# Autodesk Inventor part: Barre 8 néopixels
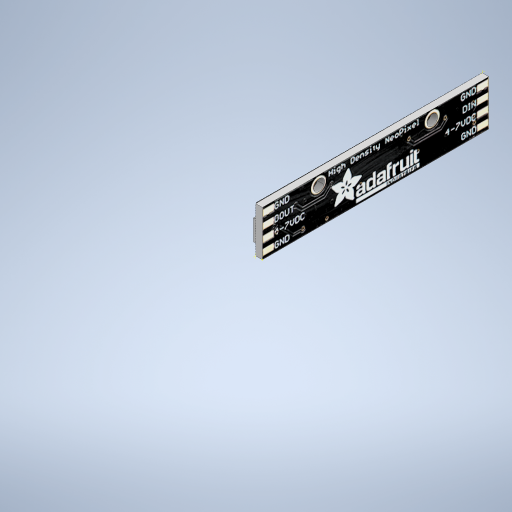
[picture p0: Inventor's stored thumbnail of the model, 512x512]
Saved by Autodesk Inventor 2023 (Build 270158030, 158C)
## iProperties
Created: 2022-11
Part Number: Barre 8 néopixels
Material: Générique
Document SubType Name: Modeling
Designer: ecuenot
Density: 1 g/cm^3
Appearance: Par défaut
Author: ecuenot
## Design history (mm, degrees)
sketch "Esquisse1"
  geometry: L1 (0, 0)-(10.22, 0); L2 (10.22, 0)-(10.22, -51.1); L3 (10.22, -51.1)-(0, -51.1); L4 (0, -51.1)-(0, 0)
  constraints: 8 end point, 2 parallel, 1 horizontal, 1 perpendicular
  dimensions: "d0" = 10.22 distance of L2.end L3.end; "d1" = 51.1 distance of L1.end L2.end
extrude "Extrusion1" new body sketch "Esquisse1" distance "d2" = 1.5; taper "d3" = 0 deg
sketch "Esquisse2"
  geometry: 1 further point
sketch "Esquisse3"
  geometry: L1 (0, 10.22)-(51.132, 10.358); L2 (51.132, 10.358)-(51.159, 0); L3 (51.159, 0)-(0.028, -0.138); L4 (0.028, -0.138)-(0, 10.22); 2 further points; 1 other entity
  constraints: 1 coincident, 2 other
feature "Décalcomanie1" sketch "Esquisse3"
sketch "Esquisse4"
  geometry: L1 (-51.1, 10.22)-(-0.031, 10.372); L2 (-0.031, 10.372)-(0, 0); L3 (0, 0)-(-51.069, -0.152); L4 (-51.069, -0.152)-(-51.1, 10.22); 2 further points; 1 other entity
  constraints: 2 coincident, 2 other
  node "Image2"
sketch "Esquisse5"
  geometry: C1 r 1.2 at (-38.346, 8.12); C2 r 1.2 at (-12.847, 8.267); 1 further point
  constraints: 2 centre point
  dimensions: "d37" = 2.4 diameter of C1; "d38" = 2.4 diameter of C2
extrude "Extrusion2" cut sketch "Esquisse5" extent not by distance; stored distance "d39" = 3; taper "d40" = 0 deg
sketch "Esquisse6"
  geometry: C1 r 1.2 at (38.346, 8.12) reference; C2 r 1.2 at (38.346, 8.12); C3 r 1.2 at (12.787, 8.12); 3 further points
  constraints: 3 coincident, 2 centre point
  dimensions: "d42" = 2.4 diameter of C2; "d43" = 2.4 diameter of C3
extrude "Extrusion3" cut sketch "Esquisse6" distance "d44" = 3; taper "d45" = 0 deg
sketch "Esquisse7"
  geometry: L1 (-50.298, 6.296)-(-45.598, 6.296); L2 (-45.598, 6.296)-(-45.598, 1.596); L3 (-45.598, 1.596)-(-50.298, 1.596); L4 (-50.298, 1.596)-(-50.298, 6.296); 1 further point
  constraints: 8 end point, 2 parallel, 1 horizontal, 1 perpendicular
  dimensions: "d46" = 4.7 distance of L2.end L3.end; "d47" = 4.7 distance of L1.end L2.end
extrude "Extrusion4" join sketch "Esquisse7" distance "d48" = 1.4; taper "d49" = 0 deg
sketch "Esquisse8"
  geometry: L1 (-50.298, 6.296)-(-45.566, 6.263); L2 (-45.566, 6.263)-(-45.598, 1.596); L3 (-45.598, 1.596)-(-50.33, 1.628); L4 (-50.33, 1.628)-(-50.298, 6.296); 3 further points; 1 other entity
  constraints: 2 coincident, 2 other
feature "Décalcomanie2" sketch "Esquisse8"
pattern_linear "Réseau rectangulaire1" dims "d53" = 6.386
sketch "Esquisse9"
  geometry: L1 (-4.7, 4.7)-(0.032, 4.668); L2 (0.032, 4.668)-(0, 0); L3 (0, 0)-(-4.732, 0.032); L4 (-4.732, 0.032)-(-4.7, 4.7); 3 further points; 1 other entity
  constraints: 2 coincident, 2 other
feature "Décalcomanie3" sketch "Esquisse9"
sketch "Esquisse10"
  geometry: L1 (-4.7, 4.7)-(0.032, 4.668); L2 (0.032, 4.668)-(0, 0); L3 (0, 0)-(-4.732, 0.032); L4 (-4.732, 0.032)-(-4.7, 4.7); 3 further points; 1 other entity
  constraints: 2 coincident, 2 other
feature "Décalcomanie4" sketch "Esquisse10"
sketch "Esquisse11"
  geometry: L1 (-4.7, 4.7)-(0.032, 4.668); L2 (0.032, 4.668)-(0, 0); L3 (0, 0)-(-4.732, 0.032); L4 (-4.732, 0.032)-(-4.7, 4.7); L5 (0, 4.7)-(-4.7, 4.7) reference; 2 further points; 1 other entity
  constraints: 2 coincident, 1 point on line, 2 other
feature "Décalcomanie5" sketch "Esquisse11"
sketch "Esquisse12"
  geometry: L1 (1.686, 4.7)-(6.418, 4.668); L2 (6.418, 4.668)-(6.386, 0); L3 (6.386, 0)-(1.654, 0.032); L4 (1.654, 0.032)-(1.686, 4.7); L5 (-4.7, 4.7)-(0.032, 4.668); L6 (0.032, 4.668)-(0, 0); L7 (0, 0)-(-4.732, 0.032); L8 (-4.732, 0.032)-(-4.7, 4.7); 5 further points; 2 other entities
  constraints: 4 coincident, 4 other
feature "Décalcomanie6" sketch "Esquisse12"
sketch "Esquisse13"
  geometry: L1 (-4.7, 4.7)-(0.032, 4.668); L2 (0.032, 4.668)-(0, 0); L3 (0, 0)-(-4.732, 0.032); L4 (-4.732, 0.032)-(-4.7, 4.7); 3 further points; 1 other entity
  constraints: 2 coincident, 2 other
  node "Image9"
sketch "Esquisse14"
  geometry: L1 (-4.7, 4.7)-(0.032, 4.668); L2 (0.032, 4.668)-(0, 0); L3 (0, 0)-(-4.732, 0.032); L4 (-4.732, 0.032)-(-4.7, 4.7); 3 further points; 1 other entity
  constraints: 2 coincident, 2 other
feature "Décalcomanie7" sketch "Esquisse14"
sketch "Esquisse15"
  geometry: L1 (-4.7, 4.7)-(0.032, 4.668); L2 (0.032, 4.668)-(0, 0); L3 (0, 0)-(-4.732, 0.032); L4 (-4.732, 0.032)-(-4.7, 4.7); 3 further points; 1 other entity
  constraints: 2 coincident, 2 other
feature "Décalcomanie8" sketch "Esquisse15"
feature "Décalcomanie9"
node "Solide1"
node "Image1"
node "Image3"
node "Image4"
node "Image5"
node "Image6"
node "Image7"
node "Image8"
node "Image10"
node "Image11"
